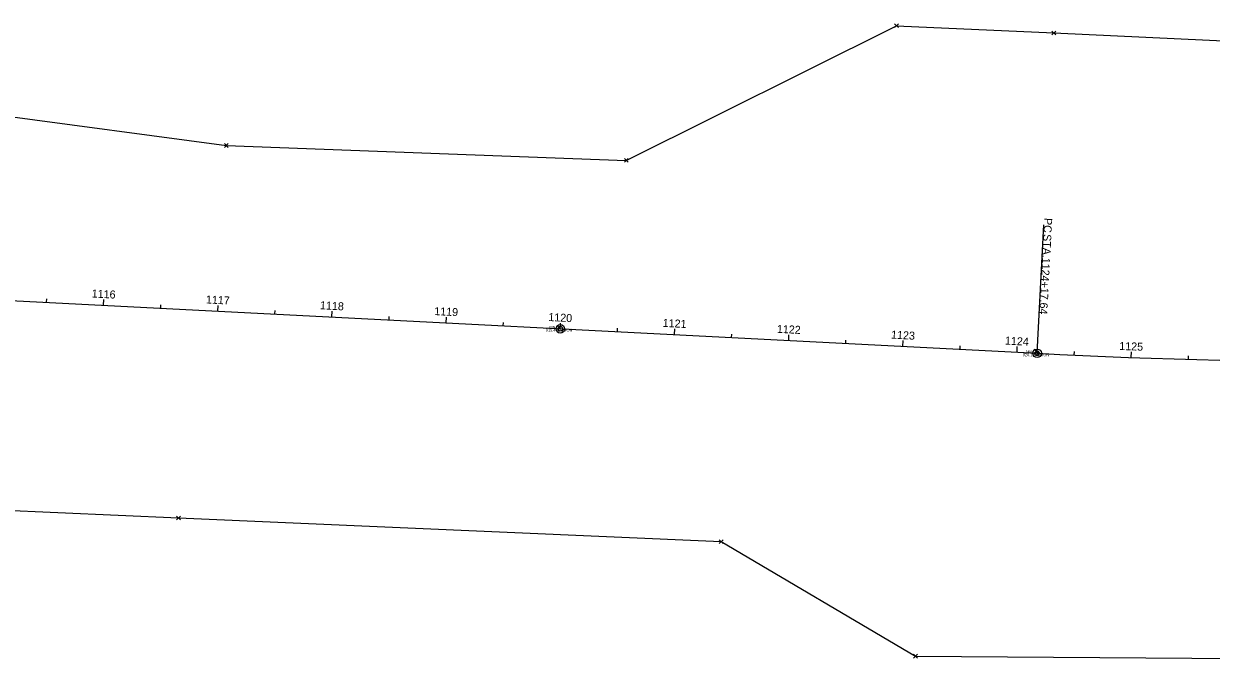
# Model space of a CAD drawing. Extents: x 2082101 to 2090447, y 708207 to 709766.
# Drawn here: x 2083142 to 2084181, y 708208 to 708764 of the extents above; entities that cross this region are included whole.
import ezdxf

# ---------------------------------------------------------------- set-up
doc = ezdxf.new("R2010")
doc.units = 0
for name, color, linetype in [('DR_X_Ditch', 7, 'Continuous'), ('DR_X_Elev_Flow', 7, 'Continuous'), ('GK_Drainage_Nodes', 7, 'Continuous'), ('SV_X_Break_Lines', 7, 'Continuous'), ('SV_X_Mon_Cells_Found', 7, 'Continuous'), ('SV_X_Shot_Marker', 7, 'Continuous'), ('SV_X_Text_Comment', 7, 'Continuous'), ('SV_X_Text_Elevation', 7, 'Continuous'), ('SV_X_Text_Name', 7, 'Continuous'), ('SV_X_Toe_of_Slope', 7, 'Continuous')]:
    doc.layers.add(name, color=color, linetype=linetype)

msp = doc.modelspace()

# ---------------------------------------------------------------- linework, layer by layer
at = {"layer": 'DR_X_Ditch'}
for p, q in [((2083669, 708644.6), (2083905.3, 708762.4)), ((2083669, 708644.6), (2083905.3, 708762.4)), ((2083905.3, 708762.4), (2084042.9, 708756.1)), ((2083905.3, 708762.4), (2084042.9, 708756.1)), ((2084042.9, 708756.1), (2084886.6, 708717.1)), ((2084042.9, 708756.1), (2084886.6, 708717.1)), ((2082772.2, 708730.9), (2083319.2, 708657.7)), ((2082772.2, 708730.9), (2083319.2, 708657.7)), ((2083319.2, 708657.7), (2083669, 708644.6)), ((2083319.2, 708657.7), (2083669, 708644.6)), ((2082321.6, 708374), (2083277.4, 708332)), ((2083277.4, 708332), (2083751.9, 708311.2)), ((2083751.9, 708311.2), (2083922, 708211.1)), ((2083922, 708211.1), (2084299.6, 708208.4))]:
    msp.add_line(p, q, dxfattribs=at)
at = {"layer": 'DR_X_Elev_Flow'}
msp.add_line((2084028.4, 708475.9), (2084034.2, 708588.3), dxfattribs=at)
msp.add_circle((2084028.4, 708475.9), 1.5, dxfattribs=at)
at = {"layer": 'GK_Drainage_Nodes'}
for p, q in [((2083161.9, 708520.6), (2083162.1, 708523.6)), ((2083211.8, 708518), (2083212.1, 708523)), ((2083261.8, 708515.4), (2083261.9, 708518.4)), ((2083311.7, 708512.8), (2083312, 708517.8)), ((2083361.7, 708510.3), (2083361.8, 708513.3)), ((2083411.6, 708507.7), (2083411.8, 708512.7)), ((2083461.5, 708505.1), (2083461.7, 708508.1)), ((2083511.5, 708502.6), (2083511.7, 708507.5)), ((2083561.4, 708500), (2083561.5, 708503)), ((2083611.3, 708497.4), (2083611.6, 708502.4)), ((2083661.3, 708494.8), (2083661.4, 708497.8)), ((2083711.2, 708492.3), (2083711.4, 708497.3)), ((2083761.1, 708489.7), (2083761.3, 708492.7)), ((2083811.1, 708487.1), (2083811.3, 708492.1)), ((2083861, 708484.6), (2083861.1, 708487.5)), ((2083910.9, 708482), (2083911.2, 708487)), ((2083960.9, 708479.4), (2083961, 708482.4)), ((2084010.8, 708476.8), (2084011, 708481.8)), ((2084060.7, 708474.4), (2084060.9, 708477.4)), ((2084110.7, 708472.3), (2084110.9, 708477.3)), ((2084160.7, 708470.6), (2084160.7, 708473.6))]:
    msp.add_line(p, q, dxfattribs=at)
at = {"layer": 'SV_X_Break_Lines'}
for p, q in [((2083903.7, 708760.8), (2083907, 708764.1)), ((2083903.7, 708764.1), (2083907, 708760.8)), ((2084041.2, 708754.4), (2084044.6, 708757.7)), ((2084041.2, 708757.7), (2084044.6, 708754.4)), ((2083317.5, 708656), (2083320.8, 708659.3)), ((2083317.5, 708659.3), (2083320.8, 708656)), ((2083667.3, 708643), (2083670.6, 708646.3)), ((2083667.3, 708646.3), (2083670.6, 708643)), ((2083275.7, 708330.3), (2083279, 708333.6)), ((2083275.7, 708333.6), (2083279, 708330.3)), ((2083750.3, 708309.6), (2083753.6, 708312.9)), ((2083750.3, 708312.9), (2083753.6, 708309.6)), ((2083920.3, 708209.4), (2083923.7, 708212.7)), ((2083920.3, 708212.7), (2083923.7, 708209.4))]:
    msp.add_line(p, q, dxfattribs=at)
at = {"layer": 'SV_X_Shot_Marker'}
msp.add_line((2082113.3, 708574.6), (2084028.4, 708475.9), dxfattribs=at)
msp.add_arc((2084323.5, 714201), 5732.7, 267.0489, 279.82352, dxfattribs=at)
at = {"layer": 'SV_X_Text_Name'}
for p, q in [((2083608.5, 708497), (2083611.9, 708500.3)), ((2083608.5, 708500.3), (2083611.9, 708497)), ((2084025.7, 708476.1), (2084029, 708479.4)), ((2084025.7, 708479.4), (2084029, 708476.1))]:
    msp.add_line(p, q, dxfattribs=at)
at = {"layer": 'SV_X_Toe_of_Slope'}
for centre, radius in [((2083611.3, 708497.4), 3.75), ((2083611.3, 708497.4), 2), ((2084028.4, 708475.9), 3.75), ((2084028.4, 708475.9), 2)]:
    msp.add_circle(centre, radius, dxfattribs=at)

# ---------------------------------------------------------------- texts
at = {"layer": 'DR_X_Elev_Flow'}
for s, p in [('PC', (2084034.6, 708594.4)), (' STA. ', (2084034, 708582.9)), ('1124+17.64', (2084032.8, 708559.7))]:
    msp.add_text(s, height=7, rotation=267.0489, dxfattribs=at).set_placement(p)
at = {"layer": 'GK_Drainage_Nodes'}
for s, rotation, p in [('1116', 357.0515, (2083201.3, 708524.8)), ('1117', 357.0515, (2083301.2, 708519.6)), ('1118', 357.0515, (2083401, 708514.5)), ('1119', 357.0515, (2083500.9, 708509.4)), ('1120', 357.0515, (2083600.7, 708504.2)), ('1121', 357.0515, (2083700.7, 708499.1)), ('1122', 357.0515, (2083800.6, 708493.9)), ('1123', 357.0515, (2083900.5, 708488.8)), ('1124', 357.0515, (2084000.1, 708483.6)), ('1125', 357.8721, (2084100.1, 708478.9))]:
    msp.add_text(s, height=7, rotation=rotation, dxfattribs=at).set_placement(p)
at = {"layer": 'SV_X_Mon_Cells_Found'}
for p in [(2083611.3, 708494.9), (2084028.4, 708473.4)]:
    msp.add_text('CMON', height=2.5, dxfattribs=at).set_placement(p)
at = {"layer": 'SV_X_Text_Comment'}
for s, p in [('915.466', (2083598.5, 708494.9)), ('920.147', (2084015.7, 708473.4))]:
    msp.add_text(s, height=2.5, dxfattribs=at).set_placement(p)
at = {"layer": 'SV_X_Text_Elevation'}
for s, p in [('MN13', (2083601.7, 708497.4)), ('MN14', (2084018.7, 708475.9))]:
    msp.add_text(s, height=2.5, dxfattribs=at).set_placement(p)

doc.saveas('drawing.dxf')
